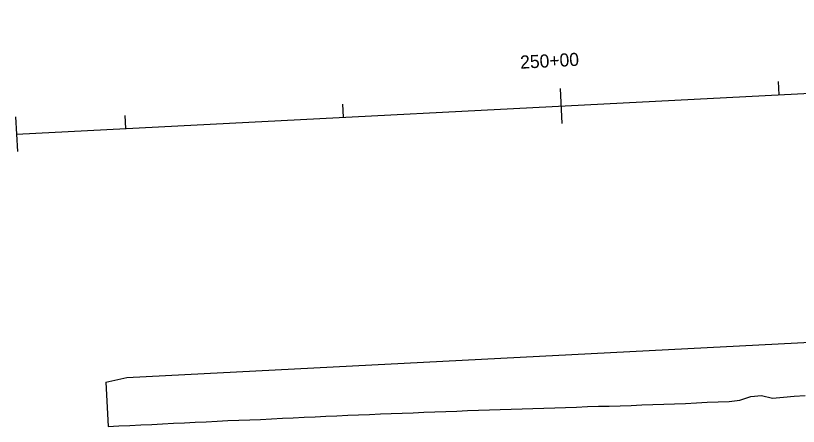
# Model space of a CAD drawing. Extents: x 1311167 to 1314552, y 2087587 to 2090602.
# Drawn here: x 1313502.7 to 1313861.6, y 2089149.9 to 2089338.1 of the extents above; entities that cross this region are included whole.
import ezdxf

# ---------------------------------------------------------------- set-up
doc = ezdxf.new("R2010")
doc.units = 0
for name, color, linetype in [('R_Proposed Road', 7, 'Continuous'), ('R_Shoulder', 7, 'Continuous'), ('S_EDGE_CONCRETE', 7, 'Continuous'), ('S_EDGE_PAVEMENT', 7, 'Continuous')]:
    doc.layers.add(name, color=color, linetype=linetype)

msp = doc.modelspace()

# ---------------------------------------------------------------- linework, layer by layer
at = {"layer": 'R_Proposed Road'}
msp.add_line((1313503.08, 2089283.78), (1314551.67, 2089338.12), dxfattribs=at)
at = {"layer": 'R_Shoulder'}
for points in [[(1313852.3, 2089307.89), (1313852.61, 2089301.9)], [(1313752.33, 2089304.71), (1313753.16, 2089288.73)], [(1313652.57, 2089297.54), (1313652.88, 2089291.55)], [(1313502.67, 2089291.77), (1313503.49, 2089275.79)], [(1313502.67, 2089291.77), (1313503.49, 2089275.79)], [(1313552.7, 2089292.36), (1313553.01, 2089286.37)]]:
    msp.add_lwpolyline(points, dxfattribs=at)
at = {"layer": 'S_EDGE_CONCRETE'}
msp.add_lwpolyline([(1313544.02, 2089170.13), (1313545.07, 2089149.88), (1313550.06, 2089150.1), (1313555.05, 2089150.34), (1313560.05, 2089150.52), (1313565.05, 2089150.78), (1313570.04, 2089151.04), (1313575.03, 2089151.3), (1313580.03, 2089151.52), (1313585.02, 2089151.74), (1313590.02, 2089152.01), (1313595.01, 2089152.27), (1313600, 2089152.52), (1313605, 2089152.67), (1313610, 2089152.81), (1313614.99, 2089153.08), (1313619.99, 2089153.35), (1313624.98, 2089153.6), (1313629.97, 2089153.83), (1313634.97, 2089154.1), (1313639.96, 2089154.31), (1313644.96, 2089154.52), (1313649.96, 2089154.73), (1313654.95, 2089154.95), (1313659.95, 2089155.18), (1313664.94, 2089155.36), (1313669.94, 2089155.55), (1313674.94, 2089155.75), (1313679.93, 2089155.94), (1313684.93, 2089156.13), (1313689.93, 2089156.32), (1313694.92, 2089156.51), (1313699.92, 2089156.72), (1313704.92, 2089156.91), (1313709.91, 2089157.09), (1313714.91, 2089157.27), (1313719.91, 2089157.42), (1313724.91, 2089157.62), (1313729.91, 2089157.75), (1313734.9, 2089157.93), (1313739.9, 2089158.11), (1313744.9, 2089158.26), (1313749.9, 2089158.4), (1313754.9, 2089158.55), (1313759.9, 2089158.73), (1313764.89, 2089158.9), (1313769.89, 2089159.08), (1313774.89, 2089159.16), (1313779.89, 2089159.32), (1313784.89, 2089159.5), (1313789.89, 2089159.68), (1313794.88, 2089159.85), (1313799.88, 2089160.04), (1313804.88, 2089160.23), (1313809.87, 2089160.42), (1313814.87, 2089160.61), (1313819.86, 2089160.97), (1313824.86, 2089161.13), (1313829.86, 2089161.25), (1313834.83, 2089161.94), (1313839.76, 2089163.49), (1313844.74, 2089163.96), (1313849.8, 2089162.83), (1313854.79, 2089163.29), (1313859.77, 2089163.75), (1313864.77, 2089163.96)], dxfattribs=at)
at = {"layer": 'S_EDGE_PAVEMENT'}
for p, q in [((1313553.62, 2089172.25), (1314203.05, 2089205.9)), ((1313544.02, 2089170.13), (1313553.62, 2089172.25))]:
    msp.add_line(p, q, dxfattribs=at)

# ---------------------------------------------------------------- texts
at = {"layer": 'R_Shoulder'}
msp.add_text('250+00', height=6, rotation=2.9667, dxfattribs=at).set_placement((1313734.19, 2089313.78))

doc.saveas('drawing.dxf')
